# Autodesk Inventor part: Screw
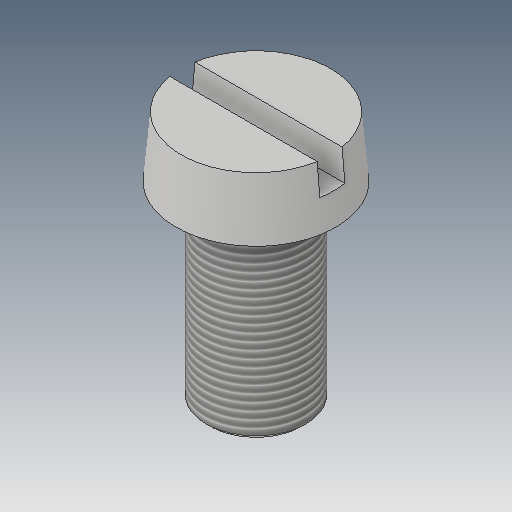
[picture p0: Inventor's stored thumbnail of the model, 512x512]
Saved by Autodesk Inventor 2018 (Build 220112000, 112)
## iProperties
Created: 2016-05
Part Number: Screw
Material: Generic
Document SubType Name: Modeling
Designer: CADCIM
Density: 1 g/cm^3
Appearance: Default
Author: CADCIM
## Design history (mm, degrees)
sketch "Sketch1"
  geometry: C1 r 16 at (0, 0); 1 further point
  constraints: 1 centre point, 1 coincident
  dimensions: "d0" = 32 diameter of C1
extrude "Extrusion1" new body sketch "Sketch1" distance "d1" = 12; taper "d2" = -5 deg
sketch "Sketch2"
  geometry: C1 r 10 at (0, 0); 1 further point
  constraints: 1 centre point, 1 coincident
  dimensions: "d4" = 20 diameter of C1
extrude "Extrusion2" join sketch "Sketch2" distance "d5" = 38; taper "d6" = 0 deg
workplane "Work Plane1"
thread "Thread1" dims "d10" = 10, "d11" = 0
chamfer "Chamfer1" distance "d12" = 0.9; stored, may be unused: second distance "d13" = 2, angle "d14" = 45 deg
sketch "Sketch4"
  geometry: L1 (-19.014, -2.5)-(20.179, -2.5); L2 (20.179, -2.5)-(20.179, 2.5); L3 (20.179, 2.5)-(-19.014, 2.5); L4 (-19.014, 2.5)-(-19.014, -2.5); L5 (0, 0)-(-19.039, 0)
  constraints: 10 end point, 2 horizontal, 2 parallel, 1 perpendicular, 1 other
  dimensions: "d15" = 5 distance of L3.end L1.start
extrude "Extrusion4" cut sketch "Sketch4" distance "d16" = 6; taper "d17" = 0 deg
body "Solid1"
